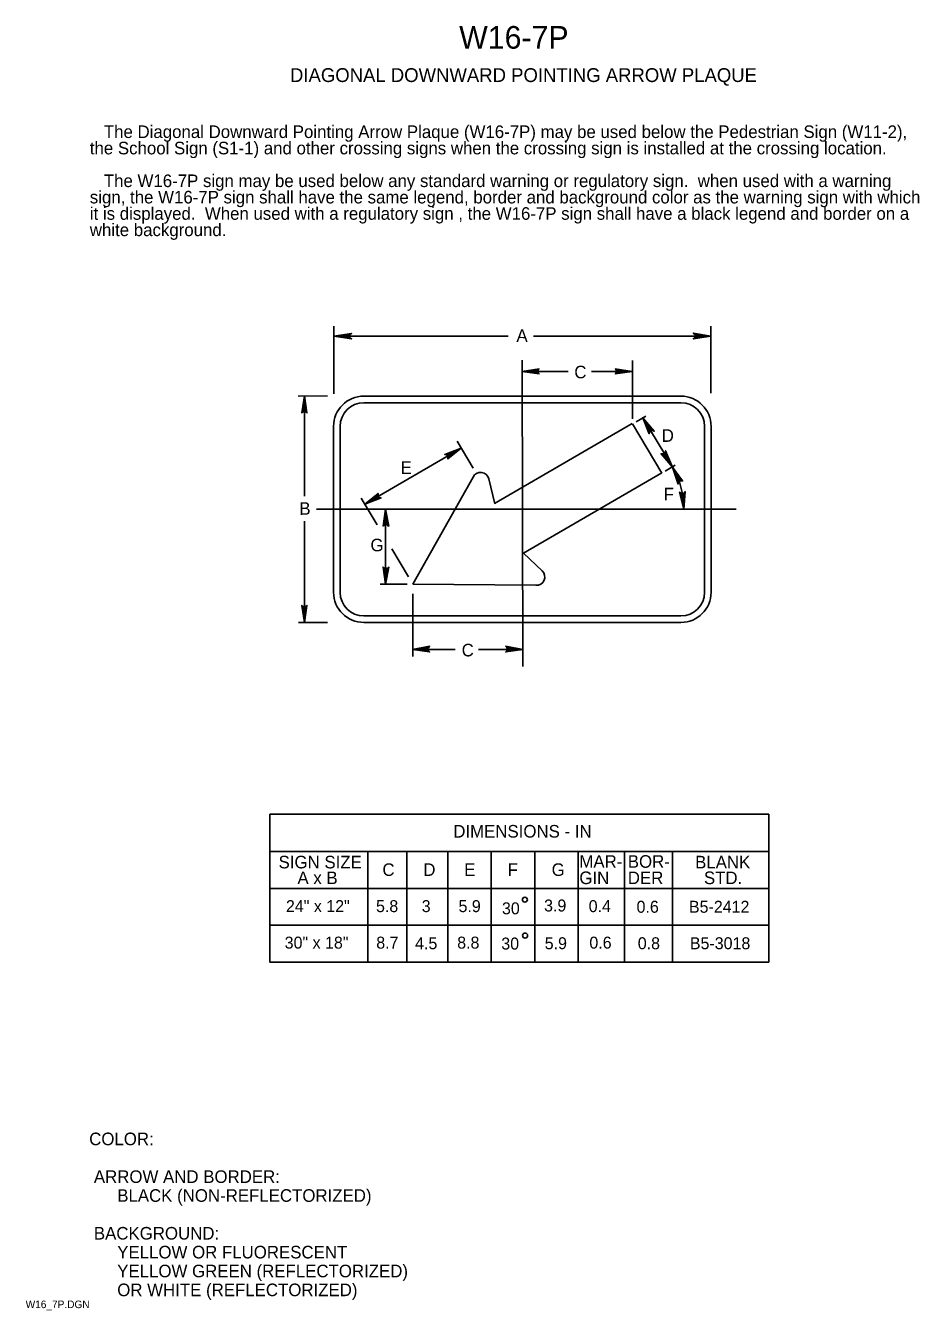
# Model space of a CAD drawing. Extents: x 0.013 to 0.19, y 0.004 to 0.259.
import ezdxf

# ---------------------------------------------------------------- set-up
doc = ezdxf.new("R2010")
doc.units = 0
for name, color, linetype in [('1', 7, 'Continuous'), ('2', 7, 'Continuous'), ('3', 7, 'Continuous')]:
    doc.layers.add(name, color=color, linetype=linetype)

msp = doc.modelspace()

# ---------------------------------------------------------------- linework, layer by layer
at = {"layer": '3'}
for p, q in [((0.07372296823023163, 0.19947868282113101), (0.07372297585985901, 0.18606225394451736)), ((0.14861871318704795, 0.19947868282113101), (0.14861872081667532, 0.18617113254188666)), ((0.07372296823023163, 0.19748638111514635), (0.108352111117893, 0.19748638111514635)), ((0.11338570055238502, 0.1975), (0.148625, 0.1975)), ((0.111125, 0.19275), (0.11125, 0.131875)), ((0.13305345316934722, 0.19263711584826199), (0.1330534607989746, 0.18107458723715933)), ((0.11121095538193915, 0.19050427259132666), (0.12030344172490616, 0.19050427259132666)), ((0.1249070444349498, 0.19050427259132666), (0.13305544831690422, 0.19050427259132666)), ((0.0724757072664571, 0.1856205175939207), (0.06661317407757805, 0.18561203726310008)), ((0.067875, 0.185625), (0.067875, 0.16567827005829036)), ((0.07967844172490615, 0.18558155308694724), (0.14267844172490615, 0.18558155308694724)), ((0.07967844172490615, 0.1842815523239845), (0.14267844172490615, 0.1842815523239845)), ((0.13378469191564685, 0.18050451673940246), (0.13571544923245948, 0.18162127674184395)), ((0.14099138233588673, 0.17152476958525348), (0.13511169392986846, 0.18127206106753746)), ((0.07367844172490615, 0.14661112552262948), (0.07367844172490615, 0.17958155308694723)), ((0.07497844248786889, 0.14661112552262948), (0.07497844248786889, 0.17958155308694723)), ((0.133, 0.180125), (0.105625, 0.16425)), ((0.1389003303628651, 0.17028297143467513), (0.13305344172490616, 0.18008155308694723)), ((0.14737844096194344, 0.17958155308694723), (0.14737844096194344, 0.14661112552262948)), ((0.14867844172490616, 0.17958155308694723), (0.14867844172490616, 0.14661112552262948)), ((0.10138416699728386, 0.1712994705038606), (0.09820287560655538, 0.17663087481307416)), ((0.079875, 0.164125), (0.099, 0.17525000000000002)), ((0.13952417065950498, 0.17067612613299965), (0.1415480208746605, 0.17184673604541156)), ((0.10138248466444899, 0.16948790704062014), (0.08942844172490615, 0.14820655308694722)), ((0.10571353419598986, 0.16418678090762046), (0.10451534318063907, 0.16916387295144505)), ((0.111375, 0.154375), (0.138875, 0.170375)), ((0.08232622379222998, 0.16003406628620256), (0.07918590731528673, 0.16529680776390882)), ((0.07025, 0.163125), (0.153625, 0.163125)), ((0.084, 0.163125), (0.084, 0.14820655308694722)), ((0.067875, 0.16076725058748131), (0.067875, 0.140625)), ((0.08852972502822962, 0.14971267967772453), (0.08522433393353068, 0.15525206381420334)), ((0.11511258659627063, 0.15088021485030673), (0.11138951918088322, 0.1543938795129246)), ((0.08292221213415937, 0.14820655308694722), (0.0882613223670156, 0.14820655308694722)), ((0.08942844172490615, 0.14820655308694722), (0.11383648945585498, 0.14800074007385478)), ((0.08943059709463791, 0.14627592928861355), (0.08940194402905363, 0.13385684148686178)), ((0.0724757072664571, 0.1406028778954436), (0.06667823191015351, 0.14059448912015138)), ((0.14267844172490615, 0.14191112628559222), (0.07967844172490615, 0.14191112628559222)), ((0.14267844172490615, 0.14061112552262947), (0.07967844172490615, 0.14061112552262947)), ((0.08944655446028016, 0.13524698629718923), (0.09780344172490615, 0.13524698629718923)), ((0.1024585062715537, 0.13524698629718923), (0.11128675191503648, 0.13524698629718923)), ((0.061, 0.10250000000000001), (0.061, 0.073125)), ((0.061, 0.10250000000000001), (0.160125, 0.10250000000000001)), ((0.160125, 0.10250000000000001), (0.160125, 0.073125)), ((0.061, 0.095125), (0.160125, 0.095125)), ((0.0805, 0.095125), (0.0805, 0.073125)), ((0.1315, 0.095125), (0.1315, 0.073125)), ((0.14100000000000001, 0.095125), (0.14100000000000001, 0.073125)), ((0.061, 0.08775000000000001), (0.160125, 0.08775000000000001)), ((0.061, 0.0805), (0.160125, 0.0805)), ((0.061, 0.073125), (0.160125, 0.073125))]:
    msp.add_line(p, q, dxfattribs=at)
for points in [[(0.077, 0.197125), (0.076875, 0.197375), (0.07375, 0.1975), (0.077, 0.197125), (0.07725, 0.197), (0.07375, 0.1975), (0.076875, 0.197625), (0.077, 0.197875), (0.07375, 0.1975), (0.07725, 0.198), (0.077, 0.197875)], [(0.145375, 0.197875), (0.1455, 0.19775), (0.148625, 0.1975), (0.145375, 0.197875), (0.145125, 0.198125), (0.148625, 0.1975), (0.1455, 0.197375), (0.145375, 0.197125), (0.148625, 0.1975), (0.145125, 0.197), (0.145375, 0.197125)], [(0.114375, 0.19012500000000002), (0.11425, 0.19037500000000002), (0.111125, 0.1905), (0.114375, 0.19012500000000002), (0.1145, 0.19), (0.111125, 0.1905), (0.11425, 0.19062500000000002), (0.114375, 0.19087500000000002), (0.111125, 0.1905), (0.1145, 0.191), (0.114375, 0.19087500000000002)], [(0.12975, 0.19087500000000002), (0.129875, 0.19062500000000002), (0.133, 0.1905), (0.12975, 0.19087500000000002), (0.129625, 0.191), (0.133, 0.1905), (0.129875, 0.19037500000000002), (0.12975, 0.19012500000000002), (0.133, 0.1905), (0.129625, 0.19), (0.12975, 0.19012500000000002)], [(0.0675, 0.182375), (0.06775, 0.1825), (0.067875, 0.185625), (0.0675, 0.182375), (0.067375, 0.18225), (0.067875, 0.185625), (0.068, 0.1825), (0.06825, 0.182375), (0.067875, 0.185625), (0.068375, 0.18225), (0.06825, 0.182375)], [(0.136375, 0.17825), (0.1365, 0.1785), (0.135125, 0.18125), (0.136375, 0.17825), (0.136375, 0.178125), (0.135125, 0.18125), (0.136875, 0.17875), (0.137125, 0.17875), (0.135125, 0.18125), (0.137375, 0.178625), (0.137125, 0.17875)], [(0.096, 0.17400000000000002), (0.09625, 0.173875), (0.099, 0.17525000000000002), (0.096, 0.17400000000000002), (0.09575, 0.17400000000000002), (0.099, 0.17525000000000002), (0.096375, 0.17350000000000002), (0.096375, 0.17325000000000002), (0.099, 0.17525000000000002), (0.096375, 0.173125), (0.096375, 0.17325000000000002)], [(0.139625, 0.17450000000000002), (0.1395, 0.17425000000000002), (0.14100000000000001, 0.1715), (0.139625, 0.17450000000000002), (0.139625, 0.17475000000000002), (0.14100000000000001, 0.1715), (0.13925, 0.174125), (0.139, 0.174125), (0.14100000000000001, 0.1715), (0.13875, 0.174125), (0.139, 0.174125)], [(0.142125, 0.168375), (0.14225000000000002, 0.168625), (0.14100000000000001, 0.1715), (0.142125, 0.168375), (0.142125, 0.168125), (0.14100000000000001, 0.1715), (0.14250000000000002, 0.16875), (0.14275000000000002, 0.16875), (0.14100000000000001, 0.1715), (0.14300000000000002, 0.16875), (0.14275000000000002, 0.16875)], [(0.082875, 0.165375), (0.082625, 0.1655), (0.079875, 0.164125), (0.082875, 0.165375), (0.083125, 0.165375), (0.079875, 0.164125), (0.0825, 0.165875), (0.0825, 0.166125), (0.079875, 0.164125), (0.0825, 0.16625), (0.0825, 0.166125)], [(0.143375, 0.166375), (0.143125, 0.16625), (0.14325000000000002, 0.163125), (0.143375, 0.166375), (0.14350000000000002, 0.166625), (0.14325000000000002, 0.163125), (0.142875, 0.16625), (0.142625, 0.166375), (0.14325000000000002, 0.163125), (0.142375, 0.1665), (0.142625, 0.166375)], [(0.083625, 0.15987500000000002), (0.083875, 0.16), (0.084, 0.163125), (0.083625, 0.15987500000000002), (0.0835, 0.15975), (0.084, 0.163125), (0.08425, 0.16), (0.084375, 0.15987500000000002), (0.084, 0.163125), (0.084625, 0.15975), (0.084375, 0.15987500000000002)], [(0.0845, 0.1515), (0.08425, 0.151375), (0.084, 0.14825), (0.0845, 0.1515), (0.084625, 0.151625), (0.084, 0.14825), (0.083875, 0.151375), (0.083625, 0.1515), (0.084, 0.14825), (0.0835, 0.151625), (0.083625, 0.1515)], [(0.06825, 0.143875), (0.068, 0.14375000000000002), (0.067875, 0.140625), (0.06825, 0.143875), (0.068375, 0.14400000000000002), (0.067875, 0.140625), (0.06775, 0.14375000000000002), (0.0675, 0.143875), (0.067875, 0.140625), (0.067375, 0.14400000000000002), (0.0675, 0.143875)], [(0.092625, 0.134875), (0.0925, 0.135125), (0.089375, 0.13525), (0.092625, 0.134875), (0.09275, 0.13475), (0.089375, 0.13525), (0.0925, 0.1355), (0.092625, 0.135625), (0.089375, 0.13525), (0.09275, 0.135875), (0.092625, 0.135625)], [(0.108, 0.13575), (0.108125, 0.1355), (0.11125, 0.13525), (0.108, 0.13575), (0.107875, 0.135875), (0.11125, 0.13525), (0.108125, 0.135125), (0.108, 0.134875), (0.11125, 0.13525), (0.107875, 0.13475), (0.108, 0.134875)], [(0.08825, 0.095), (0.08825, 0.073125)], [(0.096375, 0.095), (0.096375, 0.073125)], [(0.105, 0.095), (0.105, 0.073125)], [(0.113625, 0.095), (0.113625, 0.073125)], [(0.12225, 0.095125), (0.12225, 0.077875)], [(0.12225, 0.095), (0.12225, 0.073125)]]:
    msp.add_lwpolyline(points, dxfattribs=at)
for centre in [(0.1116769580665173, 0.08553349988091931), (0.11171190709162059, 0.07840324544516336)]:
    msp.add_circle(centre, 0.0005001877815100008, dxfattribs=at)
for centre, radius, start, end in [((0.07967844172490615, 0.17958155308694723), 0.006, 90, 180), ((0.07967844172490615, 0.17958155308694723), 0.0047, 90, 180), ((0.14267844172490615, 0.17958155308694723), 0.006, 0, 90), ((0.14267844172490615, 0.17958155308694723), 0.0047, 0, 90), ((0.12673465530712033, 0.16318763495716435), 0.016515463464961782, 359.7827050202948, 30.31850761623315), ((0.10289172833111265, 0.16877300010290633), 0.00167, 13.535858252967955, 154.65382594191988), ((0.11396636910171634, 0.14966567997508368), 0.00167, 265.5395084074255, 46.65747609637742), ((0.07967844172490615, 0.14661112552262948), 0.006, 180, 270), ((0.07967844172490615, 0.14661112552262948), 0.0047, 180, 270), ((0.14267844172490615, 0.14661112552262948), 0.006, 270, 0), ((0.14267844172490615, 0.14661112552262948), 0.0047, 270, 0)]:
    msp.add_arc(centre, radius, start, end, dxfattribs=at)

# ---------------------------------------------------------------- texts
at = {"layer": '1'}
for s, height, p in [('W16-7P', 0.0045000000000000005, (0.098625, 0.254625)), ('DIAGONAL DOWNWARD POINTING ARROW PLAQUE', 0.00275025, (0.06501675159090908, 0.248)), ('COLOR:', 0.0024997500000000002, (0.025125, 0.036749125)), (' ARROW AND BORDER:', 0.0024997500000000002, (0.025125, 0.029249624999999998)), ('      BLACK (NON-REFLECTORIZED)', 0.0024997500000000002, (0.025125, 0.025499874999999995)), (' BACKGROUND:', 0.0024997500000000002, (0.025125, 0.018000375)), ('      YELLOW OR FLUORESCENT ', 0.0024997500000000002, (0.025125, 0.014250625)), ('      YELLOW GREEN (REFLECTORIZED)', 0.0024997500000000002, (0.025125, 0.010500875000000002)), ('      OR WHITE (REFLECTORIZED)', 0.0024997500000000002, (0.025125, 0.006751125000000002)), ('W16_7P.DGN', 0.0015, (0.0125, 0.004375))]:
    msp.add_text(s, height=height, dxfattribs=at).set_placement(p)
at = {"layer": '2'}
for s, p in [('   The Diagonal Downward Pointing Arrow Plaque (W16-7P) may be used below the Pedestrian Sign (W11-2),', (0.02525, 0.23687525)), ('the School Sign (S1-1) and other crossing signs when the crossing sign is installed at the crossing location.', (0.02525, 0.23362549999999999)), ('   The W16-7P sign may be used below any standard warning or regulatory sign.  when used with a warning ', (0.02525, 0.22712600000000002)), ('sign, the W16-7P sign shall have the same legend, border and background color as the warning sign with which ', (0.02525, 0.22387625)), ('it is displayed.  When used with a regulatory sign , the W16-7P sign shall have a black legend and border on a', (0.02525, 0.2206265)), ('white background.', (0.02525, 0.21737675))]:
    msp.add_text(s, height=0.0024997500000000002, dxfattribs=at).set_placement(p)
at = {"layer": '3'}
for s, rotation, p in [('A', 359.9170833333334, (0.11, 0.196375)), ('C', 0.08291666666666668, (0.1215, 0.18912500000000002)), ('D', 0.08291666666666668, (0.138875, 0.1765)), ('E', 0.08291666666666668, (0.08700000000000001, 0.170125)), ('F', 0.08291666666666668, (0.13925, 0.164875)), ('B', 0.08291666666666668, (0.066875, 0.162)), ('G', 0.08291666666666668, (0.081, 0.15475)), ('C', 0.08291666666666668, (0.099125, 0.133875))]:
    msp.add_text(s, height=0.0024997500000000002, rotation=rotation, dxfattribs=at).set_placement(p)
for s, height, p in [('DIMENSIONS - IN', 0.0024997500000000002, (0.09745061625, 0.097875)), ('SIGN SIZE', 0.0024997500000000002, (0.06275, 0.09175)), ('C', 0.0024997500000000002, (0.083375, 0.09025)), ('D', 0.0024997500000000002, (0.0915, 0.09025)), ('E', 0.0024997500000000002, (0.099625, 0.09025)), ('F', 0.0024997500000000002, (0.10825, 0.09025)), ('G', 0.0024997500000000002, (0.117, 0.09025)), ('MAR-', 0.0024997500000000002, (0.1225, 0.091875)), ('BOR-', 0.0024997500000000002, (0.132125, 0.091875)), ('BLANK', 0.0024997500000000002, (0.1455, 0.09175)), ('A x B', 0.0024997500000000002, (0.0665, 0.088625)), ('GIN', 0.0024997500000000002, (0.1225, 0.088625)), ('DER', 0.0024997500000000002, (0.132125, 0.088625)), ('STD.', 0.0024997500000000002, (0.14725, 0.088625)), ('24" x 12"', 0.0023752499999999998, (0.06421134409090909, 0.08306237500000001)), ('5.8', 0.0023752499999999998, (0.0821055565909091, 0.08306237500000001)), ('3', 0.0023752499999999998, (0.09118161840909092, 0.08306237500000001)), ('5.9', 0.0023752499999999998, (0.09849711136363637, 0.08306237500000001)), ('30', 0.0023752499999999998, (0.107125, 0.082625)), ('3.9', 0.0023752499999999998, (0.11549711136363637, 0.08318737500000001)), ('0.4', 0.0023752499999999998, (0.12435699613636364, 0.08306237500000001)), ('0.6', 0.0023752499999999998, (0.1338685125, 0.08293737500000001)), ('B5-2412', 0.0023752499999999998, (0.1442724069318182, 0.08293737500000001)), ('30" x 18"', 0.0023752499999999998, (0.06396134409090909, 0.075812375)), ('8.7', 0.0023752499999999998, (0.08215414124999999, 0.075812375)), ('4.5', 0.0023752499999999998, (0.0898713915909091, 0.075687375)), ('8.8', 0.0023752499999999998, (0.0982305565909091, 0.075812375)), ('30', 0.0023752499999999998, (0.107, 0.075625)), ('5.9', 0.0023752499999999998, (0.11562211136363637, 0.075687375)), ('0.6', 0.0023752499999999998, (0.1244935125, 0.075812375)), ('0.8', 0.0023752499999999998, (0.1341055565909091, 0.075687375)), ('B5-3018', 0.0023752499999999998, (0.1444579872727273, 0.075687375))]:
    msp.add_text(s, height=height, dxfattribs=at).set_placement(p)

doc.saveas('drawing.dxf')
